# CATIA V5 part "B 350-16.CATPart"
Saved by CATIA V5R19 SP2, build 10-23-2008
Part number: BS 350-16
Bounding box of the stored display mesh (mm): x -15.868 to 15.868, y -15.868 to 15.868, z 0 to 82
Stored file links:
  C:\Users\Bora\Desktop\3D Katı model\B serisi\B 350\BS 350-16.CATPart
  C:\Program Files\Dassault Systemes\B19\intel_a\reffiles\standard\MetricThickPitch.txt
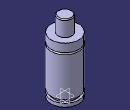
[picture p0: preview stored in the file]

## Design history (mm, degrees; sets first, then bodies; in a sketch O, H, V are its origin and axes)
Body1 (main body)
  Sketch1 on yz-plane, origin (0, 0, 0), H (0, 1, 0), V (0, 0, 1)
    point P3 (8, 81)
    point P5 (8, 81)
    point P7 (16, 54.5)
    point P8 (16, 52.5)
    point P12 (16, 52.5)
    point P13 (16, 54.5)
    line L1 (16, 0) -> (16, 4)
    line L2 (8, 81) -> (8, 64)
    arc A1 centre (7, 81) radius 1 from (8, 81) to (7, 82) ccw
    arc A2 centre (16, 53.5) radius 1 from (16, 54.5) to (16, 52.5) ccw
    line L3 (13.5, 7.5) -> (13.5, 4)
    line L4 (16, 7.5) -> (16, 52.5)
    line L5 (16, 54.5) -> (16, 64)
    line L6 (7, 82) -> (0, 82)
    point P15 (0, 82)
    line L7 (8, 64) -> (16, 64)
    line L8 (0, 0) -> (16, 0)
    line L9 (13.5, 7.5) -> (16, 7.5)
    line L10 (13.5, 4) -> (16, 4)
    coincidence: P15 V, P3 P5, P7 P13, P8 P12
    tangency: L6 A1
    horizontal: L7 H, L8 H, L9 H, L10 H
  Shaft1: profile Sketch1, axis Sketch1.V, angle 360
  Sketch2 on face of Shaft1 from Sketch1.L8, origin (0, 0, 0), H (1, 0, 0), V (0, -1, 0)
    point P1 (0, 0)
  Hole1: placed by Sketch2, at (0, 0, 0) direction (0, 0, 1), diameter 6.647, depth 7, threaded "M8", thread diameter 8, thread depth 7, pitch 1.25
